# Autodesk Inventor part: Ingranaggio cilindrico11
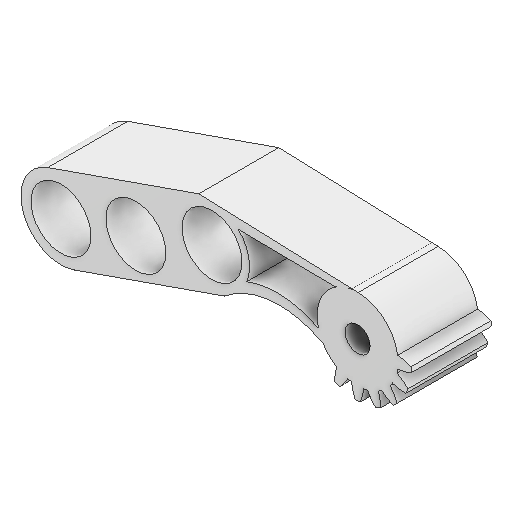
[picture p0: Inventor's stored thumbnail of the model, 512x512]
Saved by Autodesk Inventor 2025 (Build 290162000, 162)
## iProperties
Created: 2021-06
Part Number: Ingranaggio cilindrico11
Material: Plastica ABS
Document SubType Name: Modeling
Designer: Ryzen5700u
Density: 1.06 g/cm^3
Appearance: Default
Author: Ryzen5700u
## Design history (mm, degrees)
feature "Solid1"
node "Solido1"
